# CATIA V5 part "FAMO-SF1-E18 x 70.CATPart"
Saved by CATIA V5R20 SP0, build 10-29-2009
Part number: FAMO-SF1-E18 x 70
Definition: NONE
Nomenclature: FAMO-SF1-E18 x 70
Source: Unknown
Description: FAMO-SF1-E18 x 70
Bounding box of the stored display mesh (mm): x -52 to 18, y -17 to 17, z -17 to 17
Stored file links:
  C:\Users\Utente\Desktop\IO LAVORO\3D X SITO CF\X SITO\FAMO\FAMO-SF1-E18 x 70.CATPart
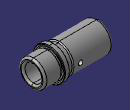
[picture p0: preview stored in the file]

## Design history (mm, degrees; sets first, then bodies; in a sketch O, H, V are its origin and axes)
Body1 "FAMO-SF1-E18 x 70" (main body)
  Solid1: solid without history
